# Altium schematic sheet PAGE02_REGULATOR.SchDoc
size 304 x 228 mm
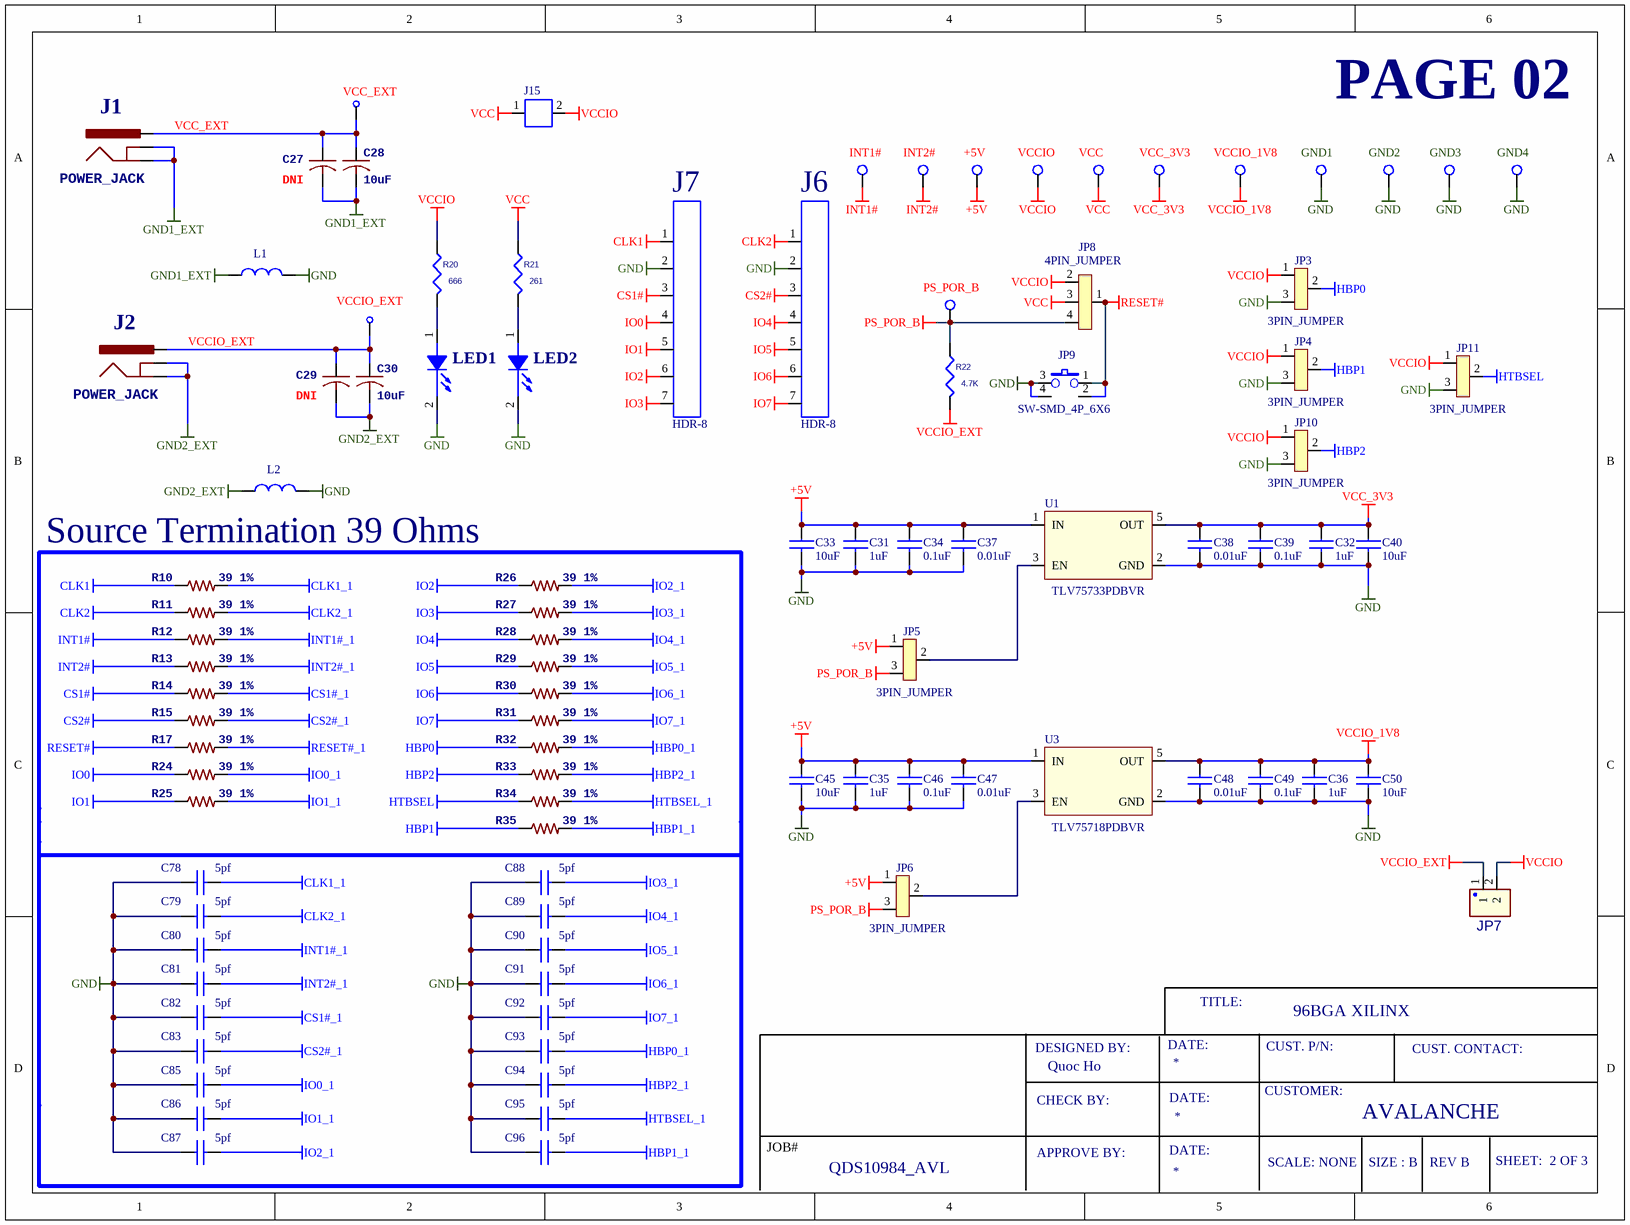
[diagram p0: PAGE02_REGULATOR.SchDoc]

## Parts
+5V  TP  [TEST POINT]  (value not drawn)
C27  DNI  [N_1206]
C28  10uF  [N_0603]
C29  DNI  [N_1206]
C30  10uF  [N_0603]
C31  1uF  [N_0603]
C32  1uF  [N_0603]
C33  10uF  [N_0603]
C34  0.1uF  [N_0603]
C35  1uF  [N_0603]
C36  1uF  [N_0603]
C37  0.01uF  [N_0603]
C38  0.01uF  [N_0603]
C39  0.1uF  [N_0603]
C40  10uF  [N_0603]
C45  10uF  [N_0603]
C46  0.1uF  [N_0603]
C47  0.01uF  [N_0603]
C48  0.01uF  [N_0603]
C49  0.1uF  [N_0603]
C50  10uF  [N_0603]
C78  5pf  [N_0402]
C79  5pf  [N_0402]
C80  5pf  [N_0402]
C81  5pf  [N_0402]
C82  5pf  [N_0402]
C83  5pf  [N_0402]
C85  5pf  [N_0402]
C86  5pf  [N_0402]
C87  5pf  [N_0402]
C88  5pf  [N_0402]
C89  5pf  [N_0402]
C90  5pf  [N_0402]
C91  5pf  [N_0402]
C92  5pf  [N_0402]
C93  5pf  [N_0402]
C94  5pf  [N_0402]
C95  5pf  [N_0402]
C96  5pf  [N_0402]
GND1  TP  [TEST POINT]  (value not drawn)
GND2  TP  [TEST POINT]  (value not drawn)
GND3  TP  [TEST POINT]  (value not drawn)
GND4  TP  [TEST POINT]  (value not drawn)
INT1#  TP  [TEST POINT]  (value not drawn)
INT2#  TP  [TEST POINT]  (value not drawn)
J1  POWER_JACK  [POWER_JACK_PTH]
J2  POWER_JACK  [POWER_JACK_PTH]
J6  HDR-8  [HDR1X7]
J7  HDR-8  [HDR1X7]
J15  (no value)  [HDR-2]
JP3  3PIN_JUMPER  [JUMPER_3PIN]
JP4  3PIN_JUMPER  [JUMPER_3PIN]
JP5  3PIN_JUMPER  [JUMPER_3PIN]
JP6  3PIN_JUMPER  [JUMPER_3PIN]
JP7  (no value)  [1X2 HEADER WITH SHUNT_051914]
JP8  4PIN_JUMPER  [JUMPER_4PIN]
JP9  SW-SMD_4P_6X6  [SW-SMD_4P_6X6]
JP10  3PIN_JUMPER  [JUMPER_3PIN]
JP11  3PIN_JUMPER  [JUMPER_3PIN]
L1  2743019447  [FB_2743019447]  (value not drawn)
L2  2743019447  [FB_2743019447]  (value not drawn)
LED1  RED  [N_0603]  (value not drawn)
LED2  RED  [N_0603]  (value not drawn)
PS_POR_B  TP  [TEST POINT]  (value not drawn)
R10  39 1%  [N_0402]
R11  39 1%  [N_0402]
R12  39 1%  [N_0402]
R13  39 1%  [N_0402]
R14  39 1%  [N_0402]
R15  39 1%  [N_0402]
R17  39 1%  [N_0402]
R20  666  [N_0603]
R21  261  [N_0603]
R22  4.7K  [N_0603]
R24  39 1%  [N_0402]
R25  39 1%  [N_0402]
R26  39 1%  [N_0402]
R27  39 1%  [N_0402]
R28  39 1%  [N_0402]
R29  39 1%  [N_0402]
R30  39 1%  [N_0402]
R31  39 1%  [N_0402]
R32  39 1%  [N_0402]
R33  39 1%  [N_0402]
R34  39 1%  [N_0402]
R35  39 1%  [N_0402]
U1  TLV75733PDBVR  [SOT23-5]
U3  TLV75718PDBVR  [SOT23-5]
VCC  TP  [TEST POINT]  (value not drawn)
VCC_3V3  TP  [TEST POINT]  (value not drawn)
VCC_EXT  TESTPOINT  [TEST POINT]  (value not drawn)
VCCIO  TP  [TEST POINT]  (value not drawn)
VCCIO_1V8  TP  [TEST POINT]  (value not drawn)
VCCIO_EXT  TESTPOINT  [TEST POINT]  (value not drawn)

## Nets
+5V: +5V.1(TP1) C31.1 C33.1 C34.1 C35.1 C37.1 C45.1 C46.1 C47.1 JP5.1 JP6.1 U1.1(IN) U3.1(IN)
CLK1: J7.1 R10.1
CLK1_1: C78.2 R10.2
CLK2: J6.1 R11.1
CLK2_1: C79.2 R11.2
CS1#: J7.3 R14.1
CS1#_1: C82.2 R14.2
CS2#: J6.3 R15.1
CS2#_1: C83.2 R15.2
GND: C31.2 C32.2 C33.2 C34.2 C35.2 C36.2 C37.2 C38.2 C39.2 C40.2 C45.2 C46.2 C47.2 C48.2 C49.2 C50.2 C78.1 C79.1 C80.1 C81.1 C82.1 C83.1 C85.1 C86.1 C87.1 C88.1 C89.1 C90.1 C91.1 C92.1 C93.1 C94.1 C95.1 C96.1 GND1.1(TP1) GND2.1(TP1) GND3.1(TP1) GND4.1(TP1) J6.2 J7.2 JP3.3 JP4.3 JP9.3 JP9.4 JP10.3 JP11.3 L1.1 L2.1 LED1.2(CATHODE) LED2.2(CATHODE) U1.2(GND) U3.2(GND)
GND1_EXT: C27.2 C28.2 J1.GND J1.GNDBREAK L1.2
GND2_EXT: C29.2 C30.2 J2.GND J2.GNDBREAK L2.2
HBP0: JP3.2 R32.1
HBP0_1: C93.2 R32.2
HBP1: JP4.2 R35.1
HBP1_1: C96.2 R35.2
HBP2: JP10.2 R33.1
HBP2_1: C94.2 R33.2
HTBSEL: JP11.2 R34.1
HTBSEL_1: C95.2 R34.2
INT1#: INT1#.1(TP1) R12.1
INT1#_1: C80.2 R12.2
INT2#: INT2#.1(TP1) R13.1
INT2#_1: C81.2 R13.2
IO0: J7.4 R24.1
IO0_1: C85.2 R24.2
IO1: J7.5 R25.1
IO1_1: C86.2 R25.2
IO2: J7.6 R26.1
IO2_1: C87.2 R26.2
IO3: J7.7 R27.1
IO3_1: C88.2 R27.2
IO4: J6.4 R28.1
IO4_1: C89.2 R28.2
IO5: J6.5 R29.1
IO5_1: C90.2 R29.2
IO6: J6.6 R30.1
IO6_1: C91.2 R30.2
IO7: J6.7 R31.1
IO7_1: C92.2 R31.2
PS_POR_B: JP5.3 JP6.3 JP8.4 PS_POR_B.1(TP1) R22.1
RESET#: JP8.1 JP9.1 JP9.2 R17.1
RESET#_1: R17.2
VCC: J15.1 JP8.3 R21.1 VCC.1(TP1)
VCC_3V3: C32.1 C38.1 C39.1 C40.1 U1.5(OUT) VCC_3V3.1(TP1)
VCCIO: J15.2 JP3.1 JP4.1 JP7.2 JP8.2 JP10.1 JP11.1 R20.1 VCCIO.1(TP1)
VCCIO_1V8: C36.1 C48.1 C49.1 C50.1 U3.5(OUT) VCCIO_1V8.1(TP1)
VCCIO_EXT: C29.1 C30.1 J2.PWR JP7.1 R22.2 VCCIO_EXT.1(TP1)
VCC_EXT: C27.1 C28.1 J1.PWR VCC_EXT.1(TP1)
NetJP5_2: JP5.2 U1.3(EN)
NetJP6_2: JP6.2 U3.3(EN)
NetLED1_1: LED1.1(ANODE) R20.2
NetLED2_1: LED2.1(ANODE) R21.2

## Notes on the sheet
- PAGE 02
- Source Termination 39 Ohms
- TITLE:
- 96BGA XILINX
- DESIGNED BY:
- CHECK BY:
- Quoc Ho
- DATE:
- CUSTOMER:
- CUST. P/N:
- CUST. CONTACT:
- JOB#
- QDS10984_AVL
- APPROVE BY:
- SCALE: NONE
- AVALANCHE
- SIZE : B
- REV B
- SHEET:  2 OF 3

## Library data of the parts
+5V GND1-GND4 INT1# INT2# PS_POR_B VCC VCC_3V3 VCC_EXT VCCIO VCCIO_1V8 VCCIO_EXT = TEST POINT 1: CONN HEADER VERT 1POS; Part Number: TSW-101-07-G-S
C27 C29 = C-USC0603
C28 C30 = C-USC0603: CAP CER 10UF 10V X5R 0603; Part Number: CL10A106MP8NNNC
C31 C32 C35 C36 = CAP: CAP CER 1UF 16V X7R 0603; Part Number: CL10B105MO8NNWC
C33 C40 C45 C50 = CAP: CAP CER 10UF 10V X5R 0603; Part Number: CL10A106MP8NNNC
C34 C39 C46 C49 = CAP: CAP CER 0.1UF 16V X7R 0603; Part Number: CL10B104KO8NNNC
C37 C38 C47 C48 = CAP: CAP CER  0.01UF 16V X7R 0603; Part Number: CL10B103KO8WPNC
C78-C83 C85-C96 = CAP: CAP CER 5PF 16V C0G/NP0 01005; Part Number: CL05C050DB5NNNC
J1 J2 = POWER_JACK: CONN PWR JACK 2X5.5MM SOLDER; Part Number: PJ-102A
J6 J7 = HDR-7: CONN HEADER VERT 7POS 2.54MM; Part Number: TSW-107-07-G-S
J15 = HDR-2PIN: CONN HEADER VERT 2POS 2.54MM; Part Number: TSW-102-07-G-S
JP3-JP6 JP10 JP11 = 3PIN_JUMPER: CONN HEADER VERT 3POS 2.54MM; Part Number: TSW-103-07-G-S
JP7 = X5511FV-10-C70D30-1000_0: CONN HEADER VERT 2POS 2.54MM; Part Number: TSW-102-07-G-S
JP8 = 4PIN_JUMPER: CONN HEADER VERT 4POS 2.54MM; Part Number: TSW-104-07-G-S
JP9 = SW PUSH-S_2: SWITCH TACTILE SPST-NO 0.05A 12V; Part Number: TL3301AF160QG
L1 L2 = INDUCTOR: Ferrite Beads 43 SM BEAD Z=47 OHM @ 100MHz
LED1 LED2 = LED: LED RED CLEAR CHIP SMD; Part Number: LTST-C190EKT
R10-R15 R17 R24-R35 = R-US_R0603: RES 39 OHM 1% 1/16W 0402; Part Number: RC0402FR-0739RL
R20 = R: RES SMD 665 OHM 1% 1/10W 0603; Part Number: RC0603FR-07665RL
R21 = R: RES SMD 261 OHM 1% 1/10W 0603; Part Number: RC0603FR-07261RL
R22 = R: RES 4.7K OHM 1% 1/10W 0603; Part Number: RC0603FR-074K7L
U1 = TLV757P: IC REG LINEAR 3.3V 1A SOT23-5
U3 = TLV757P: IC REG LINEAR 1.8V 1A SOT23-5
